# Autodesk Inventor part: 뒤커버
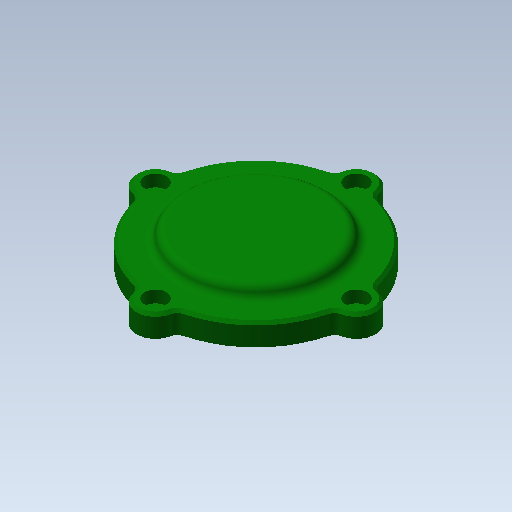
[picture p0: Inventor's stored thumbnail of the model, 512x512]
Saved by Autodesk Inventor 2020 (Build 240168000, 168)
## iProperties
Created: 2015-12
Part Number: 뒤커버
Document SubType Name: Modeling
Designer: mdu
Density: 2.71 g/cm^3
Material: 알루미늄 6061
Appearance: 진녹색
Company: 한국ATC센터
Author: mdu
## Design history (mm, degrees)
sketch "스케치1"
  geometry: C1 r 1.621 at (0, 6.75) reference; C2 r 1.621 at (-37, -30.25) reference; C3 r 1.621 at (0, -67.25) reference; C4 r 1.621 at (37, -30.25) reference; C5 r 10 at (0, -30.25) reference; C6 r 12 at (0, -30.25); C7 r 24.5 at (0, -30.25) reference; A1 r 3 centre (-38.77, -20.408) between (-38.239, -23.361) and (-35.862, -21.146) reference; A2 r 7 centre (-37, -30.25) between (-38.239, -23.361) and (-38.239, -37.139) reference; A3 r 3 centre (-38.77, -40.092) between (-35.862, -39.354) and (-38.239, -37.139) reference; A4 r 37 centre (0, -30.25) between (-35.862, -39.354) and (-9.104, -66.113) reference; A5 r 3 centre (-9.842, -69.02) between (-6.889, -68.489) and (-9.104, -66.113) reference; A6 r 7 centre (0, -67.25) between (-6.889, -68.489) and (6.889, -68.489) reference; A7 r 3 centre (9.842, -69.02) between (9.104, -66.112) and (6.889, -68.489) reference; A8 r 37 centre (0, -30.25) between (9.104, -66.112) and (35.863, -39.354) reference; A9 r 3 centre (38.77, -40.092) between (38.239, -37.139) and (35.863, -39.354) reference; A10 r 7 centre (37, -30.25) between (38.239, -37.139) and (38.239, -23.361) reference; A11 r 3 centre (38.77, -20.408) between (35.863, -21.146) and (38.239, -23.361) reference; A12 r 37 centre (0, -30.25) between (35.863, -21.146) and (9.104, 5.612) reference; A13 r 3 centre (9.842, 8.52) between (6.889, 7.989) and (9.104, 5.612) reference; A14 r 7 centre (0, 6.75) between (6.889, 7.989) and (-6.889, 7.989) reference; A15 r 3 centre (-9.842, 8.52) between (-9.104, 5.612) and (-6.889, 7.989) reference; A16 r 37 centre (0, -30.25) between (-9.104, 5.612) and (-35.862, -21.146) reference; 1 further point
  constraints: 1 centre point, 1 coincident
  dimensions: "d2" = 2 radial gap between concentric circles of C6 C5
extrude "돌출1" new body sketch "스케치1" distance "d0" = 8; taper "d1" = 0 deg
sketch "스케치2"
  geometry: C1 r 23.5 at (0, -30.25) reference; C2 r 12 at (0, -30.25) reference; 1 further point
extrude "돌출2" join sketch "스케치2" distance "d4" = 6; taper "d5" = 0 deg
sketch "스케치9"
  geometry: C1 r 23.5 at (0, 0) reference; C2 r 21 at (0, 0); 1 further point
  constraints: 1 centre point, 1 coincident
  dimensions: "d61" = 42 diameter of C2
extrude "돌출6" cut sketch "스케치9" distance "d62" = 3; taper "d63" = 0 deg
node "작업 평면1"
sketch "스케치4"
  geometry: C1 r 12 at (0, -30.25) reference; C2 r 27 at (0, -30.25); 1 further point
  constraints: 1 centre point
  dimensions: "d10" = 15 radial gap between concentric circles of C1 C2
extrude "돌출4" join sketch "스케치4" distance "d11" = 4; taper "d12" = -20 deg
fillet "모깎기2" dims "d13" = 3
node "작업점1"
  node "작업축1"
chamfer "모따기2" distance "d24" = 1; stored, may be unused: second distance "d25" = 2, angle "d26" = 45 deg
hole "구멍6" diameter "d43" = 4.5; stored, may be unused: countersink angle "d47" = 90 deg, drill point angle "d49" = 118 deg; dims "d41" = 10, "d42" = 10, "d44" = 6, "d45" = 8, "d46" = 4.4, "d48" = 8
fillet "모깎기4" dims "d60" = 3
node "솔리드1"
pattern_circular "원형 패턴1" dims angle "d51" = 360 deg
node "참조1"
node "참조2"
